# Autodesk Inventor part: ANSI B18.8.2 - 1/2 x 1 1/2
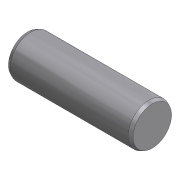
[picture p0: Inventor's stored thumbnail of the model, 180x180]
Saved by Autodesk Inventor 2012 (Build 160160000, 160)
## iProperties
Created: 2000-06
Part Number: ANSI B18.8.2 - 1/2 x 1 1/2
Material: Stainless Steel, Austenitic
Description: Pin - Unhardened Ground Dowel
Document SubType Name: Standard Catalog Part
Standard: ANSI B18.8.2 - 1/2 x 1 1/2
Designer: Ron
Density: 1 g/cm^3
Control State: 0
Master: False
Checked Out: False
Shininess: 60.0
Density: 0.0
Volumn: 0.0
Area: 0.0
PropertySet Name: Model Information
Author: Ron
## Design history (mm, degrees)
node "Base1"
body "Solid1"
